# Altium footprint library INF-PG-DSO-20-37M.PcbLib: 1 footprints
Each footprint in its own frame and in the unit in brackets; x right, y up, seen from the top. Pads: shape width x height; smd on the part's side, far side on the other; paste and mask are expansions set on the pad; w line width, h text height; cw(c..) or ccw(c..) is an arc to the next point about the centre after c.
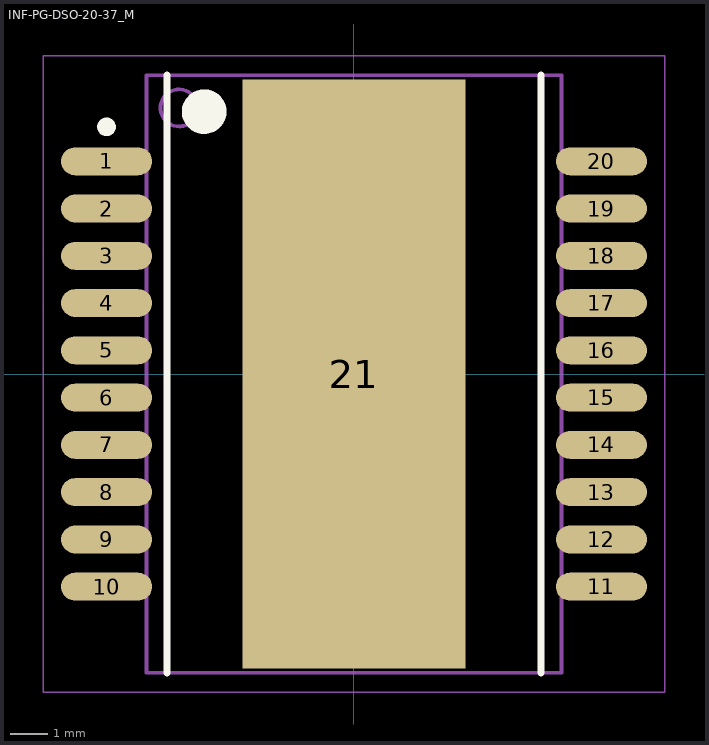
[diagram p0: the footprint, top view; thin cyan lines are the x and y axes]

## INF-PG-DSO-20-37_M [mm] "SOP, 20-Leads, Body 15.9x11mm, Pitch 1.27mm, Thermal Pad 15.84x6mm, IPC Low Density"
height 3.5
pads (21):
  oval 2.45x0.75 smd: 1(-6.65,5.715) 2(-6.65,4.445) 3(-6.65,3.175) 4(-6.65,1.905) 5(-6.65,0.635) 6(-6.65,-0.635) 7(-6.65,-1.905) 8(-6.65,-3.175) 9(-6.65,-4.445) 10(-6.65,-5.715) 11(6.65,-5.715) 12(6.65,-4.445) 13(6.65,-3.175) 14(6.65,-1.905) 15(6.65,-0.635) 16(6.65,0.635) 17(6.65,1.905) 18(6.65,3.175) 19(6.65,4.445) 20(6.65,5.715)
  rect 6x15.84 smd: 21(0,0)
Top Overlay:
  circle w0.25: c-6.65,6.64 r0.125
  circle w0.6: c-4.025,7.05 r0.3
  lines w0.2: -5.025,-8.025 -5.025,8.025 ; 5.025,-8.025 5.025,8.025
Mechanical 13:
  circle w0.1: c-4.7,7.15 r0.5
  lines w0.1: -5.575,-8.025 -5.575,8.025 5.575,8.025 5.575,-8.025 -5.575,-8.025
Mechanical 15:
  lines w0.05: -8.35,-8.55 -8.35,8.55 8.35,8.55 8.35,-8.55 -8.35,-8.55
  lines w0.1: -0.5,0 0.5,0 ; 0,-0.5 0,0.5
3D body: height 3.5, standoff 0, extent -5.575,-8.025 5.575,8.025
